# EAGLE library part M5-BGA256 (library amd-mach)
AMD MACH SERIES
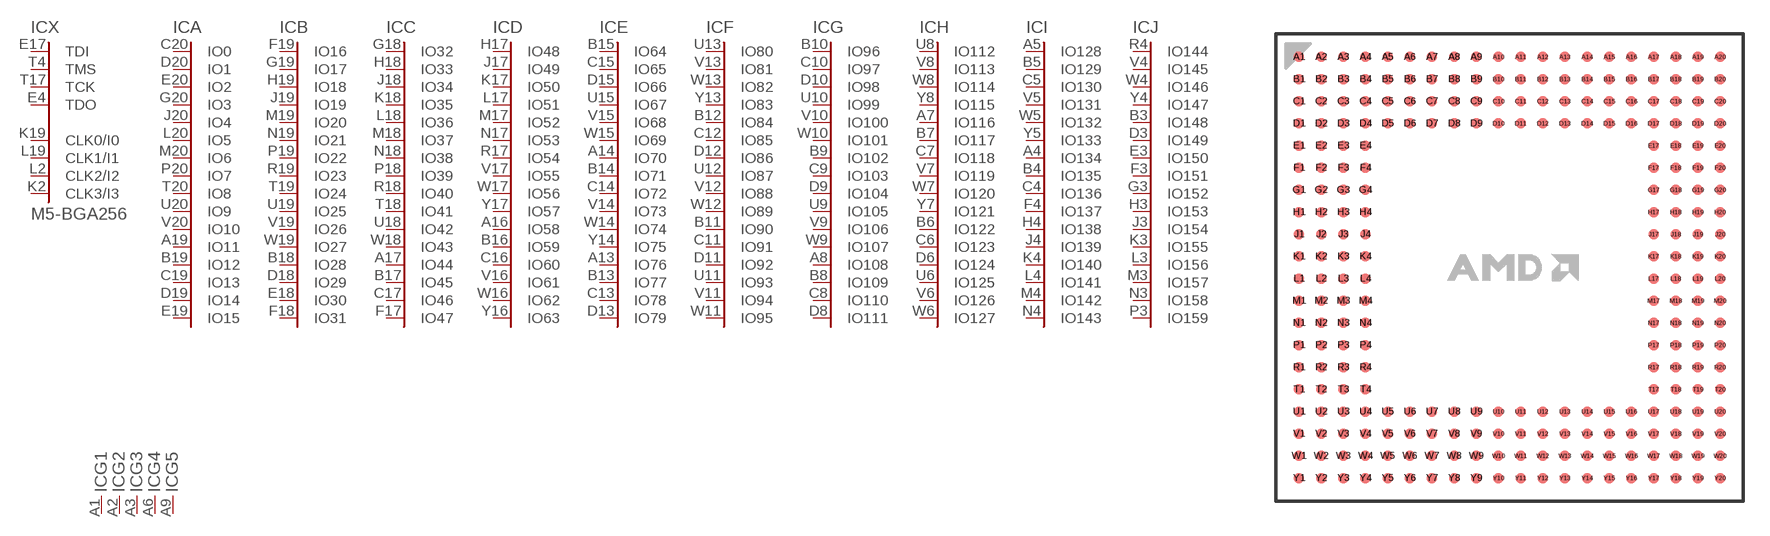
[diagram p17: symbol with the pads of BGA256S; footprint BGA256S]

Designator prefix IC; gates X=M5-CTRL A=IO15 B=IO31 C=IO47 D=IO63 E=IO79 F=IO95 G=IO111 H=IO127 I=IO143 J=IO159 G1=GND G2=GND G3=GND G4=GND G5=GND G6=GND G7=GND G8=GND G9=GND G10=GND G11=GND G12=GND G13=GND G14=GND G15=GND G16=GND G17=GND G18=GND G19=GND G20=GND G21=GND G22=GND G23=GND G24=GND G25=GND G26=GND V1=VCC V2=VCC V3=VCC V4=VCC V5=VCC V6=VCC V7=VCC V8=VCC V9=VCC V10=VCC V11=VCC V12=VCC V13=VCC V14=VCC K=IO175 L=IO191 V15=VCC V16=VCC V17=VCC V18=VCC V19=VCC V20=VCC G27=GND G28=GND G29=GND G30=GND G31=GND G32=GND G33=GND G34=GND G35=GND G36=GND

## M5-BGA256 (OC_FARNELL: unknown; OC_NEWARK: unknown)  [BGA256S]
A1  G1:GND  pwr
A2  G2:GND  pwr
A3  G3:GND  pwr
A4  I:IO134
A5  I:IO128
A6  G4:GND  pwr
A7  H:IO116
A8  G:IO108
A9  G5:GND  pwr
A10  G6:GND  pwr
A11  G7:GND  pwr
A12  G8:GND  pwr
A13  E:IO76
A14  E:IO70
A15  G9:GND  pwr
A16  D:IO58
A17  C:IO44
A18  G10:GND  pwr
A19  A:IO11
A20  G11:GND  pwr
B1  G12:GND  pwr
B2  K:IO164
B3  J:IO148
B4  I:IO135
B5  I:IO129
B6  H:IO122
B7  H:IO117
B8  G:IO109
B9  G:IO102
B10  G:IO96
B11  F:IO90
B12  F:IO84
B13  E:IO77
B14  E:IO71
B15  E:IO64
B16  D:IO59
B17  C:IO45
B18  B:IO28
B19  A:IO12
B20  G13:GND  pwr
C1  L:IO181
C2  K:IO165
C3  V1:VCC  pwr
C4  I:IO136
C5  I:IO130
C6  H:IO123
C7  H:IO118
C8  G:IO110
C9  G:IO103
C10  G:IO97
C11  F:IO91
C12  F:IO85
C13  E:IO78
C14  E:IO72
C15  E:IO65
C16  D:IO60
C17  C:IO46
C18  V2:VCC  pwr
C19  A:IO13
C20  A:IO0
D1  L:IO182
D2  K:IO166
D3  J:IO149
D4  V3:VCC  pwr
D5  V4:VCC  pwr
D6  H:IO124
D7  V5:VCC  pwr
D8  G:IO111
D9  G:IO104
D10  G:IO98
D11  F:IO92
D12  F:IO86
D13  E:IO79
D14  V6:VCC  pwr
D15  E:IO66
D16  V7:VCC  pwr
D17  V8:VCC  pwr
D18  B:IO29
D19  A:IO14
D20  A:IO1
E1  L:IO183
E2  K:IO167
E3  J:IO150
E4  X:TDO  in
E17  X:TDI  in
E18  B:IO30
E19  A:IO15
E20  A:IO2
F1  G14:GND  pwr
F2  K:IO168
F3  J:IO151
F4  I:IO137
F17  C:IO47
F18  B:IO31
F19  B:IO16
F20  G15:GND  pwr
G1  L:IO184
G2  K:IO169
G3  J:IO152
G4  V10:VCC  pwr
G17  V9:VCC  pwr
G18  C:IO32
G19  B:IO17
G20  A:IO3
H1  G16:GND  pwr
H2  K:IO170
H3  J:IO153
H4  I:IO138
H17  D:IO48
H18  C:IO33
H19  B:IO18
H20  G17:GND  pwr
J1  L:IO185
J2  K:IO171
J3  J:IO154
J4  I:IO139
J17  D:IO49
J18  C:IO34
J19  B:IO19
J20  A:IO4
K1  L:IO186
K2  X:CLK3/I3  in
K3  J:IO155
K4  I:IO140
K17  D:IO50
K18  C:IO35
K19  X:CLK0/I0  in
K20  G18:GND  pwr
L1  G19:GND  pwr
L2  X:CLK2/I2  in
L3  J:IO156
L4  I:IO141
L17  D:IO51
L18  C:IO36
L19  X:CLK1/I1  in
L20  A:IO5
M1  L:IO187
M2  K:IO172
M3  J:IO157
M4  I:IO142
M17  D:IO52
M18  C:IO37
M19  B:IO20
M20  A:IO6
N1  G20:GND  pwr
N2  K:IO173
N3  J:IO158
N4  I:IO143
N17  D:IO53
N18  C:IO38
N19  B:IO21
N20  G21:GND  pwr
P1  L:IO188
P2  K:IO174
P3  J:IO159
P4  V11:VCC  pwr
P17  V12:VCC  pwr
P18  C:IO39
P19  B:IO22
P20  A:IO7
R1  G22:GND  pwr
R2  K:IO175
R3  K:IO160
R4  J:IO144
R17  D:IO54
R18  C:IO40
R19  B:IO23
R20  G23:GND  pwr
T1  L:IO189
T2  L:IO176
T3  K:IO161
T4  X:TMS  in
T17  X:TCK  in
T18  C:IO41
T19  B:IO24
T20  A:IO8
U1  L:IO190
U2  L:IO177
U3  K:IO162
U4  V13:VCC  pwr
U5  V14:VCC  pwr
U6  H:IO125
U7  V15:VCC  pwr
U8  H:IO112
U9  G:IO105
U10  G:IO99
U11  F:IO93
U12  F:IO87
U13  F:IO80
U14  V16:VCC  pwr
U15  E:IO67
U16  V17:VCC  pwr
U17  V18:VCC  pwr
U18  C:IO42
U19  B:IO25
U20  A:IO9
V1  L:IO191
V2  L:IO178
V3  V19:VCC  pwr
V4  J:IO145
V5  I:IO131
V6  H:IO126
V7  H:IO119
V8  H:IO113
V9  G:IO106
V10  G:IO100
V11  F:IO94
V12  F:IO88
V13  F:IO81
V14  E:IO73
V15  E:IO68
V16  D:IO61
V17  D:IO55
V18  V20:VCC  pwr
V19  B:IO26
V20  A:IO10
W1  G24:GND  pwr
W2  L:IO179
W3  K:IO163
W4  J:IO146
W5  I:IO132
W6  H:IO127
W7  H:IO120
W8  H:IO114
W9  G:IO107
W10  G:IO101
W11  F:IO95
W12  F:IO89
W13  F:IO82
W14  E:IO74
W15  E:IO69
W16  D:IO62
W17  D:IO56
W18  C:IO43
W19  B:IO27
W20  G25:GND  pwr
Y1  G26:GND  pwr
Y2  L:IO180
Y3  G27:GND  pwr
Y4  J:IO147
Y5  I:IO133
Y6  G28:GND  pwr
Y7  H:IO121
Y8  H:IO115
Y9  G29:GND  pwr
Y10  G30:GND  pwr
Y11  G31:GND  pwr
Y12  G32:GND  pwr
Y13  F:IO83
Y14  E:IO75
Y15  G33:GND  pwr
Y16  D:IO63
Y17  D:IO57
Y18  G34:GND  pwr
Y19  G35:GND  pwr
Y20  G36:GND  pwr

## Footprint BGA256S (pad centres in mm)
Ball Grid Array square
smd 0.6 x 0.6: A1 -12.065,12.065; A2 -10.795,12.065; A3 -9.525,12.065; A4 -8.255,12.065; A5 -6.985,12.065; A6 -5.715,12.065; A7 -4.445,12.065; A8 -3.175,12.065; A9 -1.905,12.065; A10 -0.635,12.065; A11 0.635,12.065; A12 1.905,12.065; A13 3.175,12.065; A14 4.445,12.065; A15 5.715,12.065; A16 6.985,12.065; A17 8.255,12.065; A18 9.525,12.065; A19 10.795,12.065; A20 12.065,12.065; B1 -12.065,10.795; B2 -10.795,10.795; B3 -9.525,10.795; B4 -8.255,10.795; B5 -6.985,10.795; B6 -5.715,10.795; B7 -4.445,10.795; B8 -3.175,10.795; B9 -1.905,10.795; B10 -0.635,10.795; B11 0.635,10.795; B12 1.905,10.795; B13 3.175,10.795; B14 4.445,10.795; B15 5.715,10.795; B16 6.985,10.795; B17 8.255,10.795; B18 9.525,10.795; B19 10.795,10.795; B20 12.065,10.795; C1 -12.065,9.525; C2 -10.795,9.525; C3 -9.525,9.525; C4 -8.255,9.525; C5 -6.985,9.525; C6 -5.715,9.525; C7 -4.445,9.525; C8 -3.175,9.525; C9 -1.905,9.525; C10 -0.635,9.525; C11 0.635,9.525; C12 1.905,9.525; C13 3.175,9.525; C14 4.445,9.525; C15 5.715,9.525; C16 6.985,9.525; C17 8.255,9.525; C18 9.525,9.525; C19 10.795,9.525; C20 12.065,9.525; D1 -12.065,8.255; D2 -10.795,8.255; D3 -9.525,8.255; D4 -8.255,8.255; D5 -6.985,8.255; D6 -5.715,8.255; D7 -4.445,8.255; D8 -3.175,8.255; D9 -1.905,8.255; D10 -0.635,8.255; D11 0.635,8.255; D12 1.905,8.255; D13 3.175,8.255; D14 4.445,8.255; D15 5.715,8.255; D16 6.985,8.255; D17 8.255,8.255; D18 9.525,8.255; D19 10.795,8.255; D20 12.065,8.255; E1 -12.065,6.985; E2 -10.795,6.985; E3 -9.525,6.985; E4 -8.255,6.985; E17 8.255,6.985; E18 9.525,6.985; E19 10.795,6.985; E20 12.065,6.985; F1 -12.065,5.715; F2 -10.795,5.715; F3 -9.525,5.715; F4 -8.255,5.715; F17 8.255,5.715; F18 9.525,5.715; F19 10.795,5.715; F20 12.065,5.715; G1 -12.065,4.445; G2 -10.795,4.445; G3 -9.525,4.445; G4 -8.255,4.445; G17 8.255,4.445; G18 9.525,4.445; G19 10.795,4.445; G20 12.065,4.445; H1 -12.065,3.175; H2 -10.795,3.175; H3 -9.525,3.175; H4 -8.255,3.175; H17 8.255,3.175; H18 9.525,3.175; H19 10.795,3.175; H20 12.065,3.175; J1 -12.065,1.905; J2 -10.795,1.905; J3 -9.525,1.905; J4 -8.255,1.905; J17 8.255,1.905; J18 9.525,1.905; J19 10.795,1.905; J20 12.065,1.905; K1 -12.065,0.635; K2 -10.795,0.635; K3 -9.525,0.635; K4 -8.255,0.635; K17 8.255,0.635; K18 9.525,0.635; K19 10.795,0.635; K20 12.065,0.635; L1 -12.065,-0.635; L2 -10.795,-0.635; L3 -9.525,-0.635; L4 -8.255,-0.635; L17 8.255,-0.635; L18 9.525,-0.635; L19 10.795,-0.635; L20 12.065,-0.635; M1 -12.065,-1.905; M2 -10.795,-1.905; M3 -9.525,-1.905; M4 -8.255,-1.905; M17 8.255,-1.905; M18 9.525,-1.905; M19 10.795,-1.905; M20 12.065,-1.905; N1 -12.065,-3.175; N2 -10.795,-3.175; N3 -9.525,-3.175; N4 -8.255,-3.175; N17 8.255,-3.175; N18 9.525,-3.175; N19 10.795,-3.175; N20 12.065,-3.175; P1 -12.065,-4.445; P2 -10.795,-4.445; P3 -9.525,-4.445; P4 -8.255,-4.445; P17 8.255,-4.445; P18 9.525,-4.445; P19 10.795,-4.445; P20 12.065,-4.445; R1 -12.065,-5.715; R2 -10.795,-5.715; R3 -9.525,-5.715; R4 -8.255,-5.715; R17 8.255,-5.715; R18 9.525,-5.715; R19 10.795,-5.715; R20 12.065,-5.715; T1 -12.065,-6.985; T2 -10.795,-6.985; T3 -9.525,-6.985; T4 -8.255,-6.985; T17 8.255,-6.985; T18 9.525,-6.985; T19 10.795,-6.985; T20 12.065,-6.985; U1 -12.065,-8.255; U2 -10.795,-8.255; U3 -9.525,-8.255; U4 -8.255,-8.255; U5 -6.985,-8.255; U6 -5.715,-8.255; U7 -4.445,-8.255; U8 -3.175,-8.255; U9 -1.905,-8.255; U10 -0.635,-8.255; U11 0.635,-8.255; U12 1.905,-8.255; U13 3.175,-8.255; U14 4.445,-8.255; U15 5.715,-8.255; U16 6.985,-8.255; U17 8.255,-8.255; U18 9.525,-8.255; U19 10.795,-8.255; U20 12.065,-8.255; V1 -12.065,-9.525; V2 -10.795,-9.525; V3 -9.525,-9.525; V4 -8.255,-9.525; V5 -6.985,-9.525; V6 -5.715,-9.525; V7 -4.445,-9.525; V8 -3.175,-9.525; V9 -1.905,-9.525; V10 -0.635,-9.525; V11 0.635,-9.525; V12 1.905,-9.525; V13 3.175,-9.525; V14 4.445,-9.525; V15 5.715,-9.525; V16 6.985,-9.525; V17 8.255,-9.525; V18 9.525,-9.525; V19 10.795,-9.525; V20 12.065,-9.525; W1 -12.065,-10.795; W2 -10.795,-10.795; W3 -9.525,-10.795; W4 -8.255,-10.795; W5 -6.985,-10.795; W6 -5.715,-10.795; W7 -4.445,-10.795; W8 -3.175,-10.795; W9 -1.905,-10.795; W10 -0.635,-10.795; W11 0.635,-10.795; W12 1.905,-10.795; W13 3.175,-10.795; W14 4.445,-10.795; W15 5.715,-10.795; W16 6.985,-10.795; W17 8.255,-10.795; W18 9.525,-10.795; W19 10.795,-10.795; W20 12.065,-10.795; Y1 -12.065,-12.065; Y2 -10.795,-12.065; Y3 -9.525,-12.065; Y4 -8.255,-12.065; Y5 -6.985,-12.065; Y6 -5.715,-12.065; Y7 -4.445,-12.065; Y8 -3.175,-12.065; Y9 -1.905,-12.065; Y10 -0.635,-12.065; Y11 0.635,-12.065; Y12 1.905,-12.065; Y13 3.175,-12.065; Y14 4.445,-12.065; Y15 5.715,-12.065; Y16 6.985,-12.065; Y17 8.255,-12.065; Y18 9.525,-12.065; Y19 10.795,-12.065; Y20 12.065,-12.065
